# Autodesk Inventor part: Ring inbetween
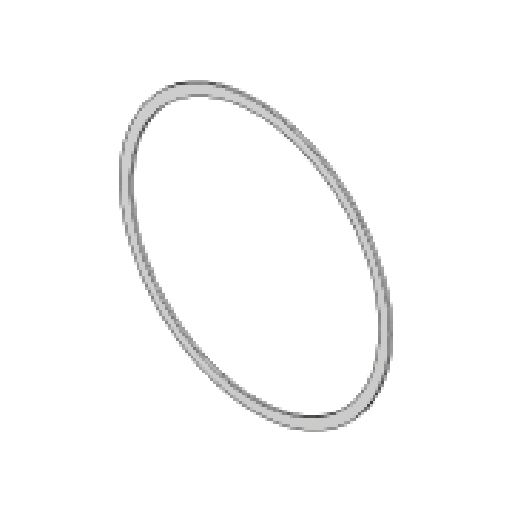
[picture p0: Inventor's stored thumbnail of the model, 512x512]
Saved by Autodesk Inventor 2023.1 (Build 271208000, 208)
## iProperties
Created: 2020-01
Part Number: Ring inbetween
Material: UHMW, White
Document SubType Name: Modeling
Designer: ftrauzettel
Density: 0.94 g/cm^3
Appearance: PTFE
Sending System: SolidWorks 2016
Last Author: Pam
Last Saved: 2020-06-07
Author: ftrauzettel
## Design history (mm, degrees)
feature "Boss-Extrude1"
body "Solid1"
